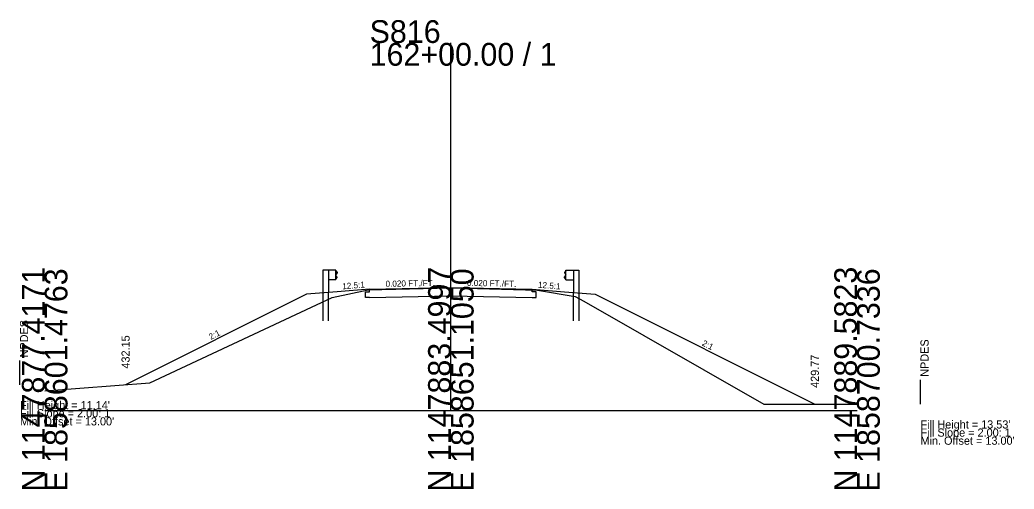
# Model space of a CAD drawing. Extents: x -76 to 4323, y -10 to 2055.
# Drawn here: x 996.9 to 1119.3, y 1990.3 to 2048.1 of the extents above; entities that cross this region are included whole.
import ezdxf

# ---------------------------------------------------------------- set-up
doc = ezdxf.new("R2010")
doc.units = 0
for name, color, linetype in [('Default', 7, 'Continuous'), ('RD_GPK_XS_Cell', 7, 'Continuous'), ('RD_XS_Base', 7, 'Continuous'), ('RD_XS_EarthShd', 7, 'Continuous'), ('RD_XS_ExGround', 7, 'Continuous'), ('RD_XS_GR', 7, 'Continuous'), ('RD_XS_NPDES', 7, 'Continuous'), ('RD_XS_Pave', 7, 'Continuous'), ('RD_XS_TieSlope', 7, 'Continuous'), ('RD_XS_TX_Elev_PR', 7, 'Continuous'), ('RD_XS_TX_ShdSlope', 7, 'Continuous'), ('RD_XS_TX_Slope', 7, 'Continuous'), ('RD_XS_TX_Warning', 7, 'Continuous')]:
    doc.layers.add(name, color=color, linetype=linetype)

msp = doc.modelspace()

# ---------------------------------------------------------------- linework, layer by layer
at = {"layer": 'Default'}
for p, q in [((1040, 2014.92), (1050, 2015.12)), ((1050, 2015.12), (1060, 2014.92))]:
    msp.add_line(p, q, dxfattribs=at)
at = {"layer": 'RD_GPK_XS_Cell'}
for p, q in [((1050, 2000), (1050, 2045.24)), ((1000, 2000), (1050, 2000)), ((1050, 2000), (1100, 2000))]:
    msp.add_line(p, q, dxfattribs=at)
at = {"layer": 'RD_XS_Base'}
for p, q in [((1040, 2013.92), (1050, 2014.12)), ((1040, 2013.92), (1050, 2014.12)), ((1050, 2014.12), (1060, 2013.92)), ((1050, 2014.12), (1060, 2013.92))]:
    msp.add_line(p, q, dxfattribs=at)
at = {"layer": 'RD_XS_EarthShd'}
for p, q in [((1036, 2014.6), (1032.25, 2014.3)), ((1036, 2014.6), (1032.25, 2014.3)), ((1040, 2014.92), (1036, 2014.6)), ((1040, 2014.92), (1036, 2014.6)), ((1060, 2014.92), (1064, 2014.6)), ((1060, 2014.92), (1064, 2014.6)), ((1064, 2014.6), (1067.75, 2014.3)), ((1064, 2014.6), (1067.75, 2014.3))]:
    msp.add_line(p, q, dxfattribs=at)
at = {"layer": 'RD_XS_ExGround'}
for p, q in [((1035.38, 2013.91), (1039.83, 2014.84)), ((1039.83, 2014.84), (1050, 2015.07)), ((1050, 2015.07), (1050.32, 2015.08)), ((1050.32, 2015.08), (1060.68, 2014.79)), ((1060.68, 2014.79), (1065.29, 2014.04)), ((1033.46, 2013.01), (1035.38, 2013.91)), ((1065.29, 2014.04), (1066.39, 2013.46)), ((1066.39, 2013.46), (1088.53, 2000.77)), ((1012.96, 2003.38), (1033.46, 2013.01)), ((1000, 2002.41), (1012.96, 2003.38)), ((1088.53, 2000.77), (1090.75, 2000.77)), ((1090.75, 2000.77), (1100, 2000.76))]:
    msp.add_line(p, q, dxfattribs=at)
at = {"layer": 'RD_XS_GR'}
for p, q in [((1034.25, 2017.25), (1034.25, 2014.46)), ((1034.92, 2017.25), (1034.25, 2017.25)), ((1034.25, 2017.25), (1034.25, 2014.46)), ((1034.92, 2017.25), (1034.25, 2017.25)), ((1034.92, 2017.25), (1034.92, 2014.51)), ((1035.83, 2017.25), (1034.92, 2017.25)), ((1034.92, 2017.25), (1034.92, 2014.51)), ((1035.83, 2017.25), (1034.92, 2017.25)), ((1035.83, 2016.09), (1035.83, 2017.25)), ((1035.83, 2016.09), (1035.83, 2017.25)), ((1035.83, 2017.18), (1036, 2016.98)), ((1035.83, 2017.18), (1036, 2016.98)), ((1036, 2016.98), (1036, 2016.93)), ((1036, 2016.98), (1036, 2016.93)), ((1064.17, 2017.18), (1064, 2016.98)), ((1064.17, 2017.18), (1064, 2016.98)), ((1064, 2016.98), (1064, 2016.93)), ((1064, 2016.98), (1064, 2016.93)), ((1064.17, 2016.09), (1064.17, 2017.25)), ((1064.17, 2017.25), (1065.08, 2017.25)), ((1064.17, 2016.09), (1064.17, 2017.25)), ((1064.17, 2017.25), (1065.08, 2017.25)), ((1065.08, 2017.25), (1065.08, 2014.51)), ((1065.08, 2017.25), (1065.75, 2017.25)), ((1065.08, 2017.25), (1065.08, 2014.51)), ((1065.08, 2017.25), (1065.75, 2017.25)), ((1065.75, 2017.25), (1065.75, 2014.46)), ((1065.75, 2017.25), (1065.75, 2014.46)), ((1035.83, 2016.09), (1034.92, 2016.09)), ((1035.83, 2016.09), (1034.92, 2016.09)), ((1036, 2016.93), (1035.83, 2016.73)), ((1036, 2016.93), (1035.83, 2016.73)), ((1036, 2016.41), (1035.83, 2016.61)), ((1036, 2016.41), (1035.83, 2016.61)), ((1035.83, 2016.16), (1036, 2016.36)), ((1035.83, 2016.16), (1036, 2016.36)), ((1036, 2016.36), (1036, 2016.41)), ((1036, 2016.36), (1036, 2016.41)), ((1064, 2016.93), (1064.17, 2016.73)), ((1064, 2016.93), (1064.17, 2016.73)), ((1064, 2016.41), (1064.17, 2016.61)), ((1064, 2016.41), (1064.17, 2016.61)), ((1064, 2016.36), (1064, 2016.41)), ((1064, 2016.36), (1064, 2016.41)), ((1064.17, 2016.16), (1064, 2016.36)), ((1064.17, 2016.16), (1064, 2016.36)), ((1064.17, 2016.09), (1065.08, 2016.09)), ((1064.17, 2016.09), (1065.08, 2016.09)), ((1034.92, 2011.04), (1034.92, 2014.51)), ((1034.92, 2011.04), (1034.92, 2014.51)), ((1065.08, 2011.04), (1065.08, 2014.51)), ((1065.08, 2011.04), (1065.08, 2014.51)), ((1034.25, 2014.46), (1034.25, 2011.04)), ((1034.25, 2014.46), (1034.25, 2011.04)), ((1065.75, 2014.46), (1065.75, 2011.04)), ((1065.75, 2014.46), (1065.75, 2011.04))]:
    msp.add_line(p, q, dxfattribs=at)
at = {"layer": 'RD_XS_NPDES'}
for p, q in [((996.96, 2003.15), (996.96, 2006.15)), ((996.96, 2003.15), (996.96, 2006.15)), ((1107.81, 2000.77), (1107.81, 2003.77)), ((1107.81, 2000.77), (1107.81, 2003.77))]:
    msp.add_line(p, q, dxfattribs=at)
at = {"layer": 'RD_XS_Pave'}
for p, q in [((1039.5, 2014.58), (1040, 2014.59)), ((1039.5, 2014.58), (1040, 2014.59)), ((1039.5, 2013.91), (1039.5, 2014.58)), ((1039.5, 2013.91), (1039.5, 2014.58)), ((1040, 2014.59), (1040, 2014.92)), ((1040, 2014.59), (1040, 2014.92)), ((1060, 2014.59), (1060, 2014.92)), ((1060, 2014.59), (1060, 2014.92)), ((1060.5, 2014.58), (1060, 2014.59)), ((1060.5, 2014.58), (1060, 2014.59)), ((1060.5, 2013.91), (1060.5, 2014.58)), ((1060.5, 2013.91), (1060.5, 2014.58)), ((1040, 2013.92), (1039.5, 2013.91)), ((1040, 2013.92), (1039.5, 2013.91)), ((1060, 2013.92), (1060.5, 2013.91)), ((1060, 2013.92), (1060.5, 2013.91))]:
    msp.add_line(p, q, dxfattribs=at)
at = {"layer": 'RD_XS_TieSlope'}
for p, q in [((1032.25, 2014.3), (1009.96, 2003.15)), ((1032.25, 2014.3), (1009.96, 2003.15)), ((1067.75, 2014.3), (1094.81, 2000.77)), ((1067.75, 2014.3), (1094.81, 2000.77))]:
    msp.add_line(p, q, dxfattribs=at)

# ---------------------------------------------------------------- texts
at = {"layer": 'RD_GPK_XS_Cell'}
for s, p in [('S816', (1040, 2045.24)), ('162+00.00 / 1', (1040, 2042.44))]:
    msp.add_text(s, height=2.8, dxfattribs=at).set_placement(p)
for s, p in [('N 1147877.4171', (1000, 1990)), ('E 1858601.4763', (1002.8, 1990)), ('N 1147883.4997', (1050, 1990)), ('E 1858651.1050', (1052.8, 1990)), ('N 1147889.5823', (1100, 1990)), ('E 1858700.7336', (1102.8, 1990))]:
    msp.add_text(s, height=2.8, rotation=90, dxfattribs=at).set_placement(p)
at = {"layer": 'RD_XS_TX_Elev_PR'}
for s, p in [('432.15', (1010.46, 2005.15)), ('432.15', (1010.46, 2005.15)), ('429.77', (1095.31, 2002.77)), ('429.77', (1095.31, 2002.77))]:
    msp.add_text(s, height=1, rotation=90, dxfattribs=at).set_placement(p)
at = {"layer": 'RD_XS_TX_ShdSlope'}
for rotation, p in [(4.5739, (1036.66, 2014.9)), (4.5739, (1036.66, 2014.9)), (355.4261, (1060.7, 2015.11)), (355.4261, (1060.7, 2015.11))]:
    msp.add_text('12.5:1', height=0.75, rotation=rotation, dxfattribs=at).set_placement(p)
at = {"layer": 'RD_XS_TX_Slope'}
for s, rotation, p in [('0.020 FT./FT.', 1.1458, (1041.97, 2015.21)), ('0.020 FT./FT.', 1.1458, (1041.97, 2015.21)), ('0.020 FT./FT.', 358.8542, (1051.98, 2015.33)), ('0.020 FT./FT.', 358.8542, (1051.98, 2015.33)), ('2:1', 26.5651, (1020.44, 2008.67)), ('2:1', 26.5651, (1020.44, 2008.67)), ('2:1', 333.4349, (1080.84, 2008.03)), ('2:1', 333.4349, (1080.84, 2008.03))]:
    msp.add_text(s, height=0.75, rotation=rotation, dxfattribs=at).set_placement(p)
at = {"layer": 'RD_XS_TX_Warning'}
for p in [(997.96, 2006.15), (997.96, 2006.15), (1108.81, 2003.77), (1108.81, 2003.77)]:
    msp.add_text(' NPDES', height=1, rotation=90, dxfattribs=at).set_placement(p)
for s, p in [("Fill Height = 11.14' ", (996.96, 2000.15)), ("Fill Height = 11.14' ", (996.96, 2000.15)), ('Fill Slope = 2.00: 1', (996.96, 1999.15)), ('Fill Slope = 2.00: 1', (996.96, 1999.15)), ("Min. Offset = 13.00' ", (996.96, 1998.15)), ("Min. Offset = 13.00' ", (996.96, 1998.15)), ("Fill Height = 13.53' ", (1107.81, 1997.77)), ("Fill Height = 13.53' ", (1107.81, 1997.77)), ('Fill Slope = 2.00: 1', (1107.81, 1996.77)), ('Fill Slope = 2.00: 1', (1107.81, 1996.77)), ("Min. Offset = 13.00' ", (1107.81, 1995.77)), ("Min. Offset = 13.00' ", (1107.81, 1995.77))]:
    msp.add_text(s, height=1, dxfattribs=at).set_placement(p)

doc.saveas('drawing.dxf')
